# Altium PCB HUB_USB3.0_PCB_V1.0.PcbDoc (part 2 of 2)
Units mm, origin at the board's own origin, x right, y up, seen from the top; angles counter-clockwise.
Board outline 100 x 80 mm, 2 copper layers (Top Layer, Bottom Layer), stack 1.071 mm thick; 154 components, 104 nets, 521 pads, 700 vias.
Unrouted connection lines stored in the file: 114.
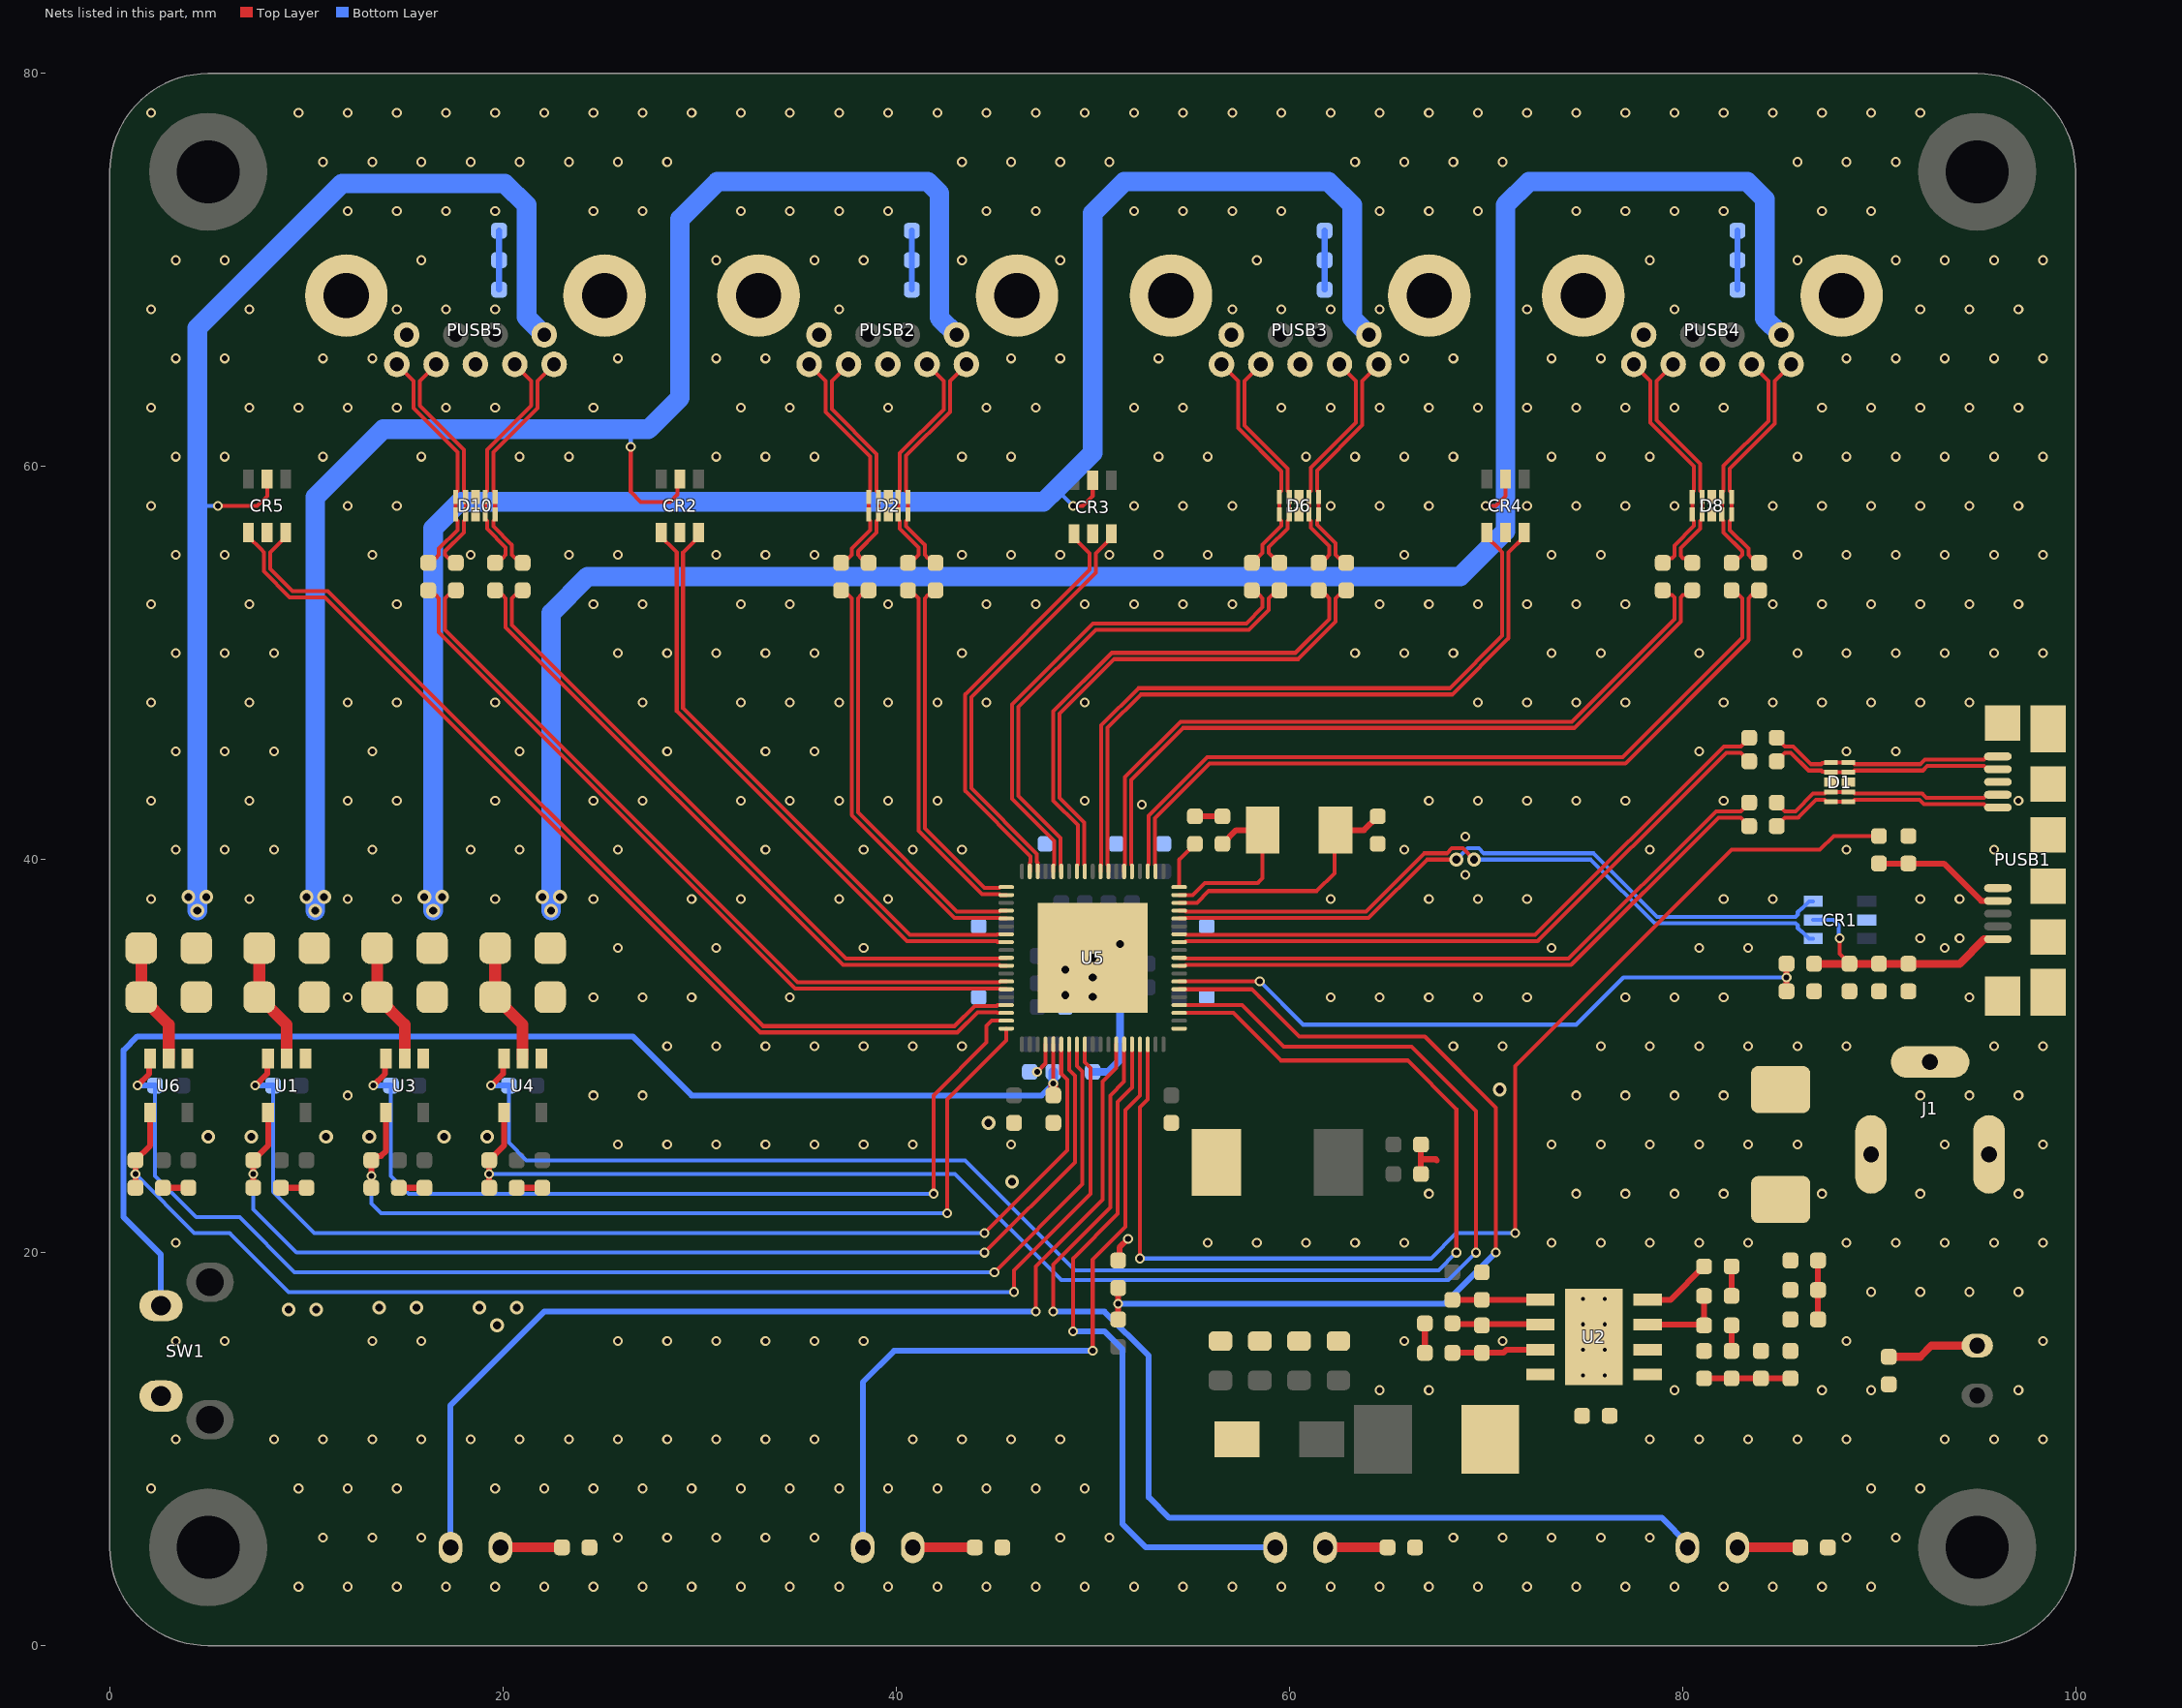
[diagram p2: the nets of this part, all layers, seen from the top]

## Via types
v1: diameter 0.5, hole 0.3, Top Layer to Bottom Layer, tented both sides, 628 vias
v2: diameter 0.7, hole 0.4, Top Layer to Bottom Layer, tented both sides, 40 vias
v3: diameter 0.8, hole 0.5, Top Layer to Bottom Layer, 32 vias

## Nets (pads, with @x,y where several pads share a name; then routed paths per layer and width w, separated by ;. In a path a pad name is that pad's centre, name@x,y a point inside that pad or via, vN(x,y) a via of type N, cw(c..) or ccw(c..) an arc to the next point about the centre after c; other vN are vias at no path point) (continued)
GND: C1.2 C2.2 C3.2 C4.1 C5.2 C6.2 C7.2 C8.2 C9.2 C10.2 C11.1 C12.1 C16.1 C17.1 C18.1 C19.1 C20.1 C21.1 C22.1 C23.1 C24.2 C25.2 C26.1 C27.2 C28.2 C29.2 C30.1 C31.1 C32.1 C33.2 C34.2 C35.2 C36.1 C37.1 C38.1 C41.1 C42.1 C43.1 C45.1 C47.1 C50.1 C51.1 C52.1 C53.1 C54.1 C55.1 C56.1 C59.1 C60.1 C61.1 C62.1 C63.1 C64.1 C65.2 C66.2 C67.2 C68.1 C69.1 C70.1 C71.2 C72.2 C73.2 C74.2 C75.1 C76.2 CR1.2 CR2.2 CR3.2 CR4.2 CR5.2 D1.3 D1.8 D2.3 D2.8 D4.1 D6.3 D6.8 D8.3 D8.8 D10.3 D10.8 J1.2 J1.3 PUSB1.5 PUSB1.8 PUSB1.SH1 PUSB1.SH2 PUSB1.SH3 PUSB1.SH4 PUSB1.SH5 PUSB1.SH6 PUSB1.SH7 PUSB1.SH8 PUSB2.4 PUSB2.7 PUSB2.SH1 PUSB2.SH2 PUSB3.4 PUSB3.7 PUSB3.SH1 PUSB3.SH2 PUSB4.4 PUSB4.7 PUSB4.SH1 PUSB4.SH2 PUSB5.4 PUSB5.7 PUSB5.SH1 PUSB5.SH2 R2.2 R4.1 R7.2 R11.1 R12.2 R13.2 R14.1 R17.1 R18.1 R21.1 R30.1 R31.1 R35.1 R39.2 R40.2 R41.1 SW1.1 U1.2 U2.7 U2.9 U2.V U3.2 U4.2 U5.23 U5.77 U6.2 | length 79.4
  Top Layer w0.2: v1(47.17,29.2) 47.6,29.63 U5.23@47.6,30.601
  Top Layer w0.3: R35.1@2.7,23.3 C64.1@4,23.3 ; R4.1@8.7,23.3 C4.1@10,23.3 ; R17.1@14.7,23.3 C26.1@16,23.3 ; R21.1@20.7,23.3 C32.1@22,23.3 ; R40.2@51.3,19.6 51.36,19.66 51.36,20.26 v1(51.8,20.7) ; R31.1@55.2,42.2 C76.2@56.6,42.2 ; C73.2@66.7,24 66.7,24.75 ; C72.2@66.7,25.5 66.7,24.75 ; 67.5,24.7 67.45,24.75 66.7,24.75 ; C25.2@68.3,14.9 C24.2@69.8,14.9 70.9,14.9 71.065,15.065 U2.7@72.775,15.065 ; C20.1@81.1,13.6 C22.1@85.5,13.6 ; R14.1@82.5,17.8 R12.2@82.5,19.3 ; C1.2@86.9,16.6 C3.2@86.9,19.6
  Top Layer w0.6: C70.1@1.6,35.5 C69.1@1.6,33 3,31.6 U6.2@3,29.875 ; C11.1@7.6,35.5 C12.1@7.6,33 9,31.6 U1.2@9,29.875 ; C31.1@13.6,35.5 C30.1@13.6,33 15,31.6 U3.2@15,29.875 ; C37.1@19.6,35.5 C36.1@19.6,33 21,31.6 U4.2@21,29.875
  Bottom Layer w0.3: C67.2@19.8,69 C66.2@19.8,72 ; C7.2@40.8,69 C5.2@40.8,72 ; C29.2@61.8,69 C27.2@61.8,72 ; C35.2@82.8,69 C34.2@82.8,72
  Bottom Layer w0.4: C41.1@50,29.2 50.8,29.2 51.4,29.8 C53.1@51.4,33.5 ; C43.1@51.4,34.7 51.4,33.7 51.3,33.6 51.3,33.4 51.2,33.3 50.4,33.3 49.6,32.5 C50.1@48.6,32.5 C52.1@48.6,33.7 C38.1@48.6,35.1 48.6,36.2 C61.1@48.4,36.4 C47.1@50.8,36.4 C45.1@52,36.4
  other v1: 9.6,3 12.1,3 14.6,3 17.1,3 19.6,3 22.1,3 24.6,3 27.1,3 29.6,3 32.1,3 34.6,3 37.1,3 39.6,3 42.1,3 44.6,3 47.1,3 49.6,3 52.1,3 54.6,3 57.1,3 59.6,3 62.1,3 64.6,3 67.1,3 69.6,3 72.1,3 74.6,3 77.1,3 79.6,3 82.1,3 84.6,3 87.1,3 89.6,3 10.85,5.5 13.35,5.5 15.85,5.5 25.85,5.5 28.35,5.5 30.85,5.5 33.35,5.5 35.85,5.5 48.35,5.5 50.85,5.5 68.35,5.5 70.85,5.5 73.35,5.5 75.85,5.5 78.35,5.5 88.35,5.5 90.85,5.5 2.1,8 9.6,8 12.1,8 14.6,8 19.6,8 22.1,8 24.6,8 27.1,8 29.6,8 32.1,8 34.6,8 37.1,8 39.6,8 42.1,8 44.6,8 47.1,8 49.6,8 89.6,8 92.1,8 3.35,10.5 8.35,10.5 10.85,10.5 13.35,10.5 15.85,10.5 18.35,10.5 20.85,10.5 23.35,10.5 25.85,10.5 28.35,10.5 30.85,10.5 33.35,10.5 35.85,10.5 40.85,10.5 43.35,10.5 45.85,10.5 48.35,10.5 78.35,10.5 80.85,10.5 83.35,10.5 85.85,10.5 88.35,10.5 93.35,10.5 95.85,10.5 98.35,10.5 64.6,13 67.1,13 79.6,13 87.1,13 89.6,13 97.1,13 3.35,15.5 5.85,15.5 13.35,15.5 15.85,15.5 25.85,15.5 28.35,15.5 30.85,15.5 33.35,15.5 35.85,15.5 38.35,15.5 65.85,15.5 70.85,15.5 88.35,15.5 98.35,15.5 89.6,18 92.1,18 94.6,18 97.1,18 3.35,20.5 55.85,20.5 58.35,20.5 60.85,20.5 63.35,20.5 65.85,20.5 73.35,20.5 75.85,20.5 78.35,20.5 80.85,20.5 83.35,20.5 88.35,20.5 90.85,20.5 93.35,20.5 95.85,20.5 98.35,20.5 67.1,23 74.6,23 77.1,23 79.6,23 82.1,23 87.1,23 92.1,23 97.1,23 25.85,25.5 28.35,25.5 30.85,25.5 33.35,25.5 35.85,25.5 38.35,25.5 40.85,25.5 45.85,25.5 73.35,25.5 75.85,25.5 78.35,25.5 80.85,25.5 83.35,25.5 85.85,25.5 93.35,25.5 98.35,25.5 12.1,28 24.6,28 27.1,28 74.6,28 77.1,28 79.6,28 82.1,28 92.1,28 94.6,28 97.1,28 28.35,30.5 30.85,30.5 33.35,30.5 35.85,30.5 38.35,30.5 40.85,30.5 43.35,30.5 68.35,30.5 70.85,30.5 75.85,30.5 78.35,30.5 80.85,30.5 83.35,30.5 85.85,30.5 88.35,30.5 95.85,30.5 98.35,30.5 12.1,33 24.6,33 27.1,33 29.6,33 34.6,33 62.1,33 64.6,33 67.1,33 69.6,33 72.1,33 77.1,33 79.6,33 82.1,33 94.6,33 25.85,35.5 30.85,35.5 38.35,35.5 73.35,35.5 80.85,35.5 83.35,35.5 93.35,35.5 92.1,36 94.1,36 2.1,38 7.1,38 12.1,38 14.6,38 19.6,38 24.6,38 29.6,38 32.1,38 37.1,38 39.6,38 62.1,38 67.1,38 69.6,38 72.1,38 82.1,38 84.6,38 92.1,38 94.1,38 68.949,39.227 3.35,40.5 5.85,40.5 8.35,40.5 13.35,40.5 18.35,40.5 20.85,40.5 25.85,40.5 33.35,40.5 38.35,40.5 40.85,40.5 43.35,40.5 65.85,40.5 78.35,40.5 88.35,40.5 95.85,40.5 68.959,41.164 52.5,42.8 2.1,43 7.1,43 12.1,43 14.6,43 19.6,43 24.6,43 27.1,43 32.1,43 34.6,43 37.1,43 39.6,43 42.1,43 49.6,43 67.1,43 69.6,43 72.1,43 74.6,43 77.1,43 82.1,43 97.1,43 3.35,45.5 5.85,45.5 8.35,45.5 13.35,45.5 20.85,45.5 28.35,45.5 33.35,45.5 35.85,45.5 80.85,45.5 88.35,45.5 90.85,45.5 2.1,48 7.1,48 12.1,48 14.6,48 19.6,48 27.1,48 32.1,48 34.6,48 37.1,48 39.6,48 42.1,48 44.6,48 49.6,48 69.6,48 72.1,48 74.6,48 77.1,48 82.1,48 84.6,48 87.1,48 89.6,48 92.1,48 94.6,48 3.35,50.5 5.85,50.5 8.35,50.5 25.85,50.5 28.35,50.5 30.85,50.5 33.35,50.5 35.85,50.5 43.35,50.5 63.35,50.5 65.85,50.5 68.35,50.5 73.35,50.5 75.85,50.5 80.85,50.5 85.85,50.5 88.35,50.5 90.85,50.5 93.35,50.5 95.85,50.5 98.35,50.5 2.1,53 7.1,53 14.6,53 24.6,53 27.1,53 32.1,53 34.6,53 39.6,53 44.6,53 47.1,53 49.6,53 52.1,53 54.6,53 57.1,53 64.6,53 67.1,53 69.6,53 72.1,53 74.6,53 77.1,53 84.6,53 87.1,53 89.6,53 92.1,53 94.6,53 97.1,53 3.35,55.5 5.85,55.5 13.35,55.5 18.35,55.5 23.35,55.5 25.85,55.5 30.85,55.5 33.35,55.5 35.85,55.5 43.35,55.5 45.85,55.5 48.35,55.5 50.85,55.5 53.35,55.5 55.85,55.5 65.85,55.5 73.35,55.5 75.85,55.5 85.85,55.5 88.35,55.5 90.85,55.5 93.35,55.5 95.85,55.5 98.35,55.5 2.1,58 12.1,58 14.6,58 52.1,58 54.6,58 57.1,58 62.1,58 64.6,58 67.1,58 72.1,58 74.6,58 77.1,58 79.6,58 84.6,58 87.1,58 89.6,58 92.1,58 94.6,58 97.1,58 3.35,60.5 5.85,60.5 10.85,60.5 15.85,60.5 20.85,60.5 23.35,60.5 30.85,60.5 33.35,60.5 35.85,60.5 43.35,60.5 45.85,60.5 53.35,60.5 55.85,60.5 60.85,60.5 63.35,60.5 65.85,60.5 68.35,60.5 73.35,60.5 75.85,60.5 78.35,60.5 85.85,60.5 88.35,60.5 90.85,60.5 93.35,60.5 95.85,60.5 98.35,60.5 2.1,63 7.1,63 9.6,63 12.1,63 14.6,63 17.1,63 19.6,63 24.6,63 32.1,63 34.6,63 39.6,63 44.6,63 47.1,63 52.1,63 54.6,63 59.6,63 62.1,63 64.6,63 67.1,63 69.6,63 72.1,63 74.6,63 77.1,63 79.6,63 82.1,63 87.1,63 89.6,63 92.1,63 94.6,63 97.1,63 3.35,65.5 5.85,65.5 10.85,65.5 13.35,65.5 25.85,65.5 30.85,65.5 33.35,65.5 45.85,65.5 48.35,65.5 53.35,65.5 65.85,65.5 68.35,65.5 73.35,65.5 75.85,65.5 88.35,65.5 90.85,65.5 93.35,65.5 95.85,65.5 98.35,65.5 2.1,68 7.1,68 14.6,68 17.1,68 19.6,68 37.1,68 57.1,68 59.6,68 62.1,68 64.6,68 72.1,68 79.6,68 92.1,68 94.6,68 97.1,68 3.35,70.5 5.85,70.5 15.85,70.5 30.85,70.5 35.85,70.5 38.35,70.5 43.35,70.5 48.35,70.5 58.35,70.5 78.35,70.5 85.85,70.5 90.85,70.5 93.35,70.5 95.85,70.5 98.35,70.5 12.1,73 14.6,73 17.1,73 19.6,73 24.6,73 27.1,73 32.1,73 34.6,73 37.1,73 39.6,73 44.6,73 47.1,73 52.1,73 54.6,73 57.1,73 59.6,73 64.6,73 67.1,73 69.6,73 74.6,73 77.1,73 79.6,73 82.1,73 87.1,73 89.6,73 10.85,75.5 13.35,75.5 15.85,75.5 18.35,75.5 20.85,75.5 23.35,75.5 25.85,75.5 28.35,75.5 43.35,75.5 45.85,75.5 48.35,75.5 50.85,75.5 63.35,75.5 65.85,75.5 68.35,75.5 70.85,75.5 85.85,75.5 88.35,75.5 90.85,75.5 2.1,78 9.6,78 12.1,78 14.6,78 17.1,78 19.6,78 22.1,78 24.6,78 27.1,78 29.6,78 32.1,78 34.6,78 37.1,78 39.6,78 42.1,78 44.6,78 47.1,78 49.6,78 52.1,78 54.6,78 57.1,78 59.6,78 62.1,78 64.6,78 67.1,78 69.6,78 72.1,78 74.6,78 77.1,78 79.6,78 82.1,78 84.6,78 87.1,78 89.6,78 92.1,78
  other v2: 19.7,16.3 9.1,17.1 10.5,17.1 13.7,17.2 15.6,17.2 18.8,17.2 20.7,17.2 45.9,23.6 5,25.9 7.2,25.9 11,25.9 13.2,25.9 17,25.9 19.2,25.9 44.7,26.6 70.7,28.3 50,33.008 48.6,33.1 50,34 48.6,34.4 50,35 51.4,35.7
HSD1_N: CR2.1 U5.8 | length 31
  Top Layer w0.2: CR2.1@28.05,56.638 28.05,56.43 28.712,55.769 28.84,55.64 28.84,47.56 40.561,35.839 45.123,35.839 45.162,35.8 U5.8@45.601,35.8
HSD1_P: CR2.3 U5.7 | length 30.5
  Top Layer w0.2: CR2.3@29.95,56.638 29.95,56.43 29.16,55.64 29.16,47.693 40.693,36.159 45.123,36.159 45.162,36.199 U5.7@45.601,36.199
HSD2_N: CR3.1 U5.75 | length 21.5
  Top Layer w0.2: U5.75@46.8,39.399 46.8,39.836 46.84,39.876 46.84,40.16 43.5,43.5 43.5,48.4 49.84,54.74 49.84,55.578 49.712,55.706 49.05,56.368 CR3.1@49.05,56.575
HSD2_P: CR3.3 U5.74 | length 21.5
  Top Layer w0.2: U5.74@47.201,39.399 47.201,39.836 47.16,39.876 47.16,40.292 43.82,43.633 43.82,48.267 50.16,54.607 50.16,55.578 50.95,56.368 CR3.3@50.95,56.575
HSD3_N: CR4.1 U5.66 | length 35.3
  Top Layer w0.2: U5.66@50.401,39.399 50.401,39.699 50.441,39.739 50.441,41.722 50.441,46.841 52.32,48.72 68.167,48.72 70.84,51.393 70.84,55.64 70.712,55.769 70.05,56.43 CR4.1@70.05,56.638
HSD3_P: CR4.3 U5.65 | length 35.3
  Top Layer w0.2: U5.65@50.8,39.399 50.8,39.699 50.761,39.739 50.761,41.59 50.761,46.708 52.453,48.4 68.3,48.4 71.16,51.26 71.16,55.64 71.95,56.43 CR4.3@71.95,56.638
HSD4_N: CR5.1 U5.17 | length 50.2
  Top Layer w0.2: CR5.1@7.05,56.638 7.05,56.43 7.712,55.769 7.84,55.64 7.84,54.66 9.15,53.35 10.95,53.35 33.094,31.206 43.106,31.206 44.139,32.239 45.124,32.239 45.164,32.199 U5.17@45.601,32.199
HSD4_P: CR5.3 U5.16 | length 49.7
  Top Layer w0.2: CR5.3@8.95,56.638 8.95,56.43 8.16,55.64 8.16,54.793 9.283,53.67 11.083,53.67 33.226,31.526 42.974,31.526 44.006,32.559 45.124,32.559 45.164,32.6 U5.16@45.601,32.6
LED1: D5.1 U5.35 | length 37.4
  Top Layer w0.2: v1(50,15) 50,19.65 51.66,21.31 51.66,27.26 52.4,28 U5.35@52.4,30.601
  Bottom Layer w0.3: D5.1@38.307,5 38.307,13.407 39.9,15 v1(50,15)
LED2: D7.1 U5.34 | length 35.9
  Top Layer w0.2: v1(49,16) 49,19.7 51.28,21.98 51.28,27.68 51.999,28.399 U5.34@51.999,30.601
  Bottom Layer w0.3: v1(49,16) 50.6,16 51.519,15.081 51.519,6.181 52.7,5 D7.1@59.283,5
LED3: D9.1 U5.33 | length 56.7
  Top Layer w0.2: v1(48,17) 48,19.4 50.9,22.3 50.9,28 51.6,28.7 U5.33@51.6,30.601
  Bottom Layer w0.3: v1(48,17) 50.6,17 52.849,14.751 52.849,7.551 53.9,6.5 78.96,6.5 80.26,5.2 D9.1@80.26,5
LED4: D11.1 U5.32 | length 54.3
  Top Layer w0.2: v1(47.1,17) 47.1,19.3 50.5,22.7 50.5,28.7 51.201,29.401 U5.32@51.201,30.601
  Bottom Layer w0.3: D11.1@17.33,5 17.33,12.23 22.1,17 v1(47.1,17)
LX: L2.1 U5.39
MAIN_D_N: CR1.4 U5.54 | length 35.6
  Top Layer w0.2: U5.54@54.399,37.398 54.699,37.398 54.739,37.358 63.906,37.358 66.867,40.32 68.014,40.32 68.264,40.57 68.83,40.57 v2(69.4,40)
  Bottom Layer w0.2: v2(69.4,40) 75.347,40 78.579,36.768 85.752,36.768 85.869,36.651 85.869,36.525 86.045,36.349 86.077,36.349 86.448,35.978 CR1.4@86.655,35.978
MAIN_D_P: CR1.6 U5.53 | length 35.6
  Top Layer w0.2: U5.53@54.399,36.999 54.699,36.999 54.739,37.038 64.038,37.038 67,40 v2(68.5,40)
  Bottom Layer w0.2: v2(68.5,40) 69.07,40.57 69.636,40.57 69.886,40.32 75.48,40.32 78.712,37.088 85.752,37.088 85.869,37.206 85.869,37.332 86.045,37.507 86.077,37.507 86.448,37.878 CR1.6@86.655,37.878
MAIN_SSRX_N: R5.2 U5.50 | length 33.2
  Top Layer w0.2: U5.50@54.399,35.8 54.699,35.8 54.739,35.839 72.639,35.839 82.24,45.44 82.983,45.44 83.4,45.023 R5.2@83.4,45
MAIN_SSRX_P: R6.2 U5.51 | length 33.2
  Top Layer w0.2: U5.51@54.399,36.199 54.699,36.199 54.739,36.159 72.507,36.159 82.107,45.76 82.983,45.76 83.4,46.177 R6.2@83.4,46.2
MAIN_SSTX_N: C13.2 U5.47 | length 32.3
  Top Layer w0.2: U5.47@54.399,34.599 54.699,34.599 54.74,34.639 74.339,34.639 81.84,42.14 82.983,42.14 83.4,41.723 C13.2@83.4,41.7
MAIN_SSTX_P: C14.2 U5.48 | length 32.3
  Top Layer w0.2: U5.48@54.399,35 54.699,35 54.74,34.959 74.207,34.959 81.707,42.46 82.983,42.46 83.4,42.877 C14.2@83.4,42.9
NetC15_1: C15.1 L1.1 U2.8
NetC15_2: C15.2 U2.1
NetC24_1: C24.1 R9.2 U2.6 | length 4.5
  Top Layer w0.3: R9.2@68.3,16.4 68.332,16.368 72.742,16.368 U2.6@72.775,16.335
NetC25_1: C25.1 R9.1 | length 1.5
  Top Layer w0.3: C25.1@66.9,14.9 R9.1@66.9,16.4
NetD3_2: D3.2 R7.1 | length 4.7
  Top Layer w0.4: R7.1@90.5,14.7 92.1,14.7 92.67,15.27 D3.2@95,15.27
NetD5_2: D5.2 R11.2 | length 3.2
  Top Layer w0.5: D5.2@40.823,5 R11.2@44,5
NetD7_2: D7.2 R18.2 | length 3.2
  Top Layer w0.5: D7.2@61.823,5 R18.2@65,5
NetD9_2: D9.2 R30.2 | length 3.2
  Top Layer w0.5: D9.2@82.823,5 R30.2@86,5
NetD11_2: D11.2 R41.2 | length 3.2
  Top Layer w0.5: D11.2@19.823,5 R41.2@23,5
NetR8_1: R8.1 R13.1 U2.5 | length 4.5
  Top Layer w0.3: R8.1@68.3,17.6 68.302,17.603 72.773,17.603 U2.5@72.775,17.605
NetR10_1: R10.1 R14.2 U2.3 | length 4.4
  Top Layer w0.3: U2.3@78.225,16.335 81.065,16.335 R10.1@81.1,16.3 R14.2@81.1,17.8
NetR12_1: R12.1 U2.4 | length 3.6
  Top Layer w0.3: U2.4@78.225,17.605 79.405,17.605 R12.1@81.1,19.3
NetR31_2: R31.2 U5.57 | length 2.5
  Top Layer w0.2: U5.57@54.399,38.599 54.399,39.999 R31.2@55.2,40.8
NetR34_2: R34.2 U5.36 | length 62.6
  Top Layer w0.2: v1(52.4,19.7) 52.4,27.4 52.799,27.799 U5.36@52.799,30.601 ; v1(71.5,21) 71.5,29.5 82.5,40.5 87,40.5 87.7,41.2 R34.2@90,41.2
  Bottom Layer w0.2: v1(52.4,19.7) 67.2,19.7 68.5,21 v1(71.5,21)
OC_PORT1: R1.2 U1.3 U5.25 | length 56.4
  Top Layer w0.2: v1(44.5,21) 48.7,25.2 48.7,28.8 48.4,29.1 U5.25@48.4,30.601
  Top Layer w0.3: v1(7.4,28.5) 8.001,29.101 U1.3@8.001,29.826
  Bottom Layer w0.2: R1.2@8.3,28.5 8.3,23.1 10.4,21 v1(44.5,21)
  Bottom Layer w0.3: v1(7.4,28.5) R1.2@8.3,28.5
OC_PORT2: R15.2 U3.3 U5.18 | length 45.8
  Top Layer w0.2: v1(41.9,23) 41.9,28 44.6,30.7 44.6,31.537 44.862,31.8 U5.18@45.601,31.8
  Top Layer w0.3: v1(13.4,28.5) 14.001,29.101 U3.3@14.001,29.826
  Bottom Layer w0.2: R15.2@14.3,28.5 14.3,23.9 15.2,23 v1(41.9,23)
  Bottom Layer w0.3: v1(13.4,28.5) R15.2@14.3,28.5
OC_PORT3: R19.2 U4.3 U5.41 | length 80.1
  Top Layer w0.2: U5.41@54.399,32.198 57.152,32.198 59.573,29.778 66.022,29.778 68.5,27.3 v1(68.5,20)
  Top Layer w0.3: v1(19.4,28.5) 20.001,29.101 U4.3@20.001,29.826
  Bottom Layer w0.2: R19.2@20.3,28.5 20.3,25.6 21.2,24.7 43.5,24.7 49.1,19.1 67.6,19.1 v1(68.5,20)
  Bottom Layer w0.3: v1(19.4,28.5) R19.2@20.3,28.5
OC_PORT4: R32.2 U5.27 U6.3 | length 65.4
  Top Layer w0.2: v1(45,19) 49.48,23.48 49.48,29.22 49.2,29.5 U5.27@49.2,30.601
  Top Layer w0.3: v1(1.4,28.5) 2.001,29.101 2.001,29.826 U6.3@2.05,29.875
  Bottom Layer w0.2: R32.2@2.3,28.5 2.3,23.9 4.4,21.8 6.6,21.8 9.4,19 v1(45,19)
  Bottom Layer w0.3: v1(1.4,28.5) R32.2@2.3,28.5
PE_PORT1: R3.2 R4.2 U1.4 U5.26 | length 56.7
  Top Layer w0.2: v1(44.5,20) 49.1,24.6 49.1,29 48.801,29.299 U5.26@48.801,30.601
  Top Layer w0.3: R4.2@7.3,23.3 R3.2@7.3,24.7 8.05,25.45 U1.4@8.05,27.125
  Bottom Layer w0.2: v1(7.3,24) 7.3,22.2 9.5,20 v1(44.5,20)
PE_PORT2: R16.2 R17.2 U3.4 U5.19 | length 46.2
  Top Layer w0.2: v1(42.6,22) 42.6,27.8 45.601,30.801 U5.19@45.601,31.398
  Top Layer w0.3: R17.2@13.3,23.3 R16.2@13.3,24.45 ; U3.4@14.05,27.125 14.05,25.181 13.788,24.919 13.546,24.919 13.45,24.823 R16.2@13.45,24.7 ; R16.2@13.3,24.45 R16.2@13.3,24.7 R16.2@13.45,24.7 ; R16.2@13.3,24.45 13.45,24.6 R16.2@13.45,24.7
  Bottom Layer w0.2: v1(13.3,23.9) 13.3,22.5 13.8,22 v1(42.6,22)
PE_PORT3: R20.2 R21.2 U4.4 U5.42 | length 81.7
  Top Layer w0.2: U5.42@54.399,32.6 57.6,32.6 59.722,30.478 66.222,30.478 69.5,27.2 v1(69.5,20)
  Top Layer w0.3: R21.2@19.3,23.3 v1(19.3,24) R20.2@19.3,24.7 20.05,25.45 U4.4@20.05,27.125
  Bottom Layer w0.2: v1(19.3,24) 43,24 48.4,18.6 68.1,18.6 v1(69.5,20)
PE_PORT4: R33.2 R35.2 U5.28 U6.4 | length 65.7
  Top Layer w0.2: v1(46,18) 46,19.1 49.9,23 49.9,29.4 49.601,29.699 U5.28@49.601,30.601
  Top Layer w0.3: R35.2@1.3,23.3 R33.2@1.3,24.7 2.05,25.45 U6.4@2.05,27.125
  Bottom Layer w0.2: v1(1.3,24) 4.3,21 6.1,21 9.1,18 v1(46,18)
POW_DET: R38.2 R40.1 U5.44 | length 47.9
  Top Layer w0.2: U5.44@54.399,33.4 58.1,33.4 58.5,33 60.5,31 66.9,31 70.517,27.383 v1(70.517,20.017)
  Top Layer w0.3: R38.2@51.3,16.6 v1(51.3,17.4) R40.1@51.3,18.2
  Bottom Layer w0.3: v1(51.3,17.4) 67.9,17.4 v1(70.517,20.017)
RESET: C75.2 R36.2 SW1.2 U5.24 | length 66.1
  Top Layer w0.2: v1(48.001,28.6) U5.24@48.001,30.601
  Top Layer w0.5: C75.2@48,28 v1(48.001,28.6)
  Bottom Layer w0.3: SW1.2@2.6,17.3 2.6,19.9 0.7,21.8 0.7,30.3 1.4,31 26.6,31 29.6,28 47.401,28 v1(48.001,28.6)
  Bottom Layer w0.5: v1(48.001,28.6) R36.2@48,29.2
RX0_N: D1.4 D1.7 PUSB1.9 R5.1 | length 12.1
  Top Layer w0.2: R5.1@84.8,45 84.8,45.023 85.217,45.44 85.507,45.44 86.414,44.533 87.059,44.533 87.122,44.47 87.528,44.47 D1.7@87.555,44.443 88.673,44.443 88.763,44.533 92.233,44.533 92.465,44.765 95.333,44.765 95.498,44.6 PUSB1.9@96.05,44.6
RX0_P: D1.5 D1.6 PUSB1.10 R6.1 | length 12.1
  Top Layer w0.2: R6.1@84.8,46.2 84.8,46.177 85.217,45.76 85.64,45.76 86.547,44.853 87.059,44.853 87.122,44.916 87.529,44.916 D1.6@87.556,44.943 88.673,44.943 88.763,44.853 92.101,44.853 92.332,45.085 95.333,45.085 95.498,45.25 PUSB1.10@96.05,45.25
RX1_N: R23.2 U5.5 | length 21.8
  Top Layer w0.2: R23.2@37.2,53.7 37.438,53.462 37.577,53.462 37.74,53.299 37.74,42.266 42.967,37.038 45.261,37.038 45.301,36.999 U5.5@45.601,36.999
RX1_P: R22.2 U5.4 | length 21.3
  Top Layer w0.2: R22.2@38.6,53.7 38.362,53.462 38.223,53.462 38.06,53.299 38.06,42.398 43.1,37.358 45.261,37.358 45.301,37.398 U5.4@45.601,37.398
RX2_N: R24.1 U5.72 | length 25.4
  Top Layer w0.2: U5.72@48.001,39.399 48.001,39.699 48.04,39.739 48.04,40.96 45.9,43.1 45.9,47.9 50.02,52.02 57.82,52.02 58.64,52.84 58.64,53.299 58.477,53.462 58.338,53.462 R24.1@58.1,53.7
RX2_P: R25.1 U5.71 | length 25.4
  Top Layer w0.2: U5.71@48.4,39.399 48.4,39.699 48.36,39.739 48.36,41.092 46.22,43.233 46.22,47.767 50.153,51.7 57.953,51.7 58.96,52.707 58.96,53.299 59.123,53.462 59.262,53.462 R25.1@59.5,53.7
RX3_N: R28.1 U5.63 | length 37.9
  Top Layer w0.2: U5.63@51.6,39.399 51.6,39.699 51.64,39.739 51.64,44.192 54.467,47.02 74.367,47.02 79.59,52.243 79.59,53.349 79.473,53.466 79.234,53.466 R28.1@79,53.7
RX3_P: R29.1 U5.62 | length 37.9
  Top Layer w0.2: U5.62@51.999,39.399 51.999,39.699 51.96,39.739 51.96,44.06 54.6,46.7 74.5,46.7 79.91,52.11 79.91,53.349 80.027,53.466 80.266,53.466 R29.1@80.5,53.7
RX4_N: R27.2 U5.14 | length 38.8
  Top Layer w0.2: R27.2@16.2,53.7 16.438,53.462 16.577,53.462 16.74,53.299 16.74,51.56 34.861,33.439 45.261,33.439 45.301,33.4 U5.14@45.601,33.4
RX4_P: R26.2 U5.13 | length 38.3
  Top Layer w0.2: R26.2@17.6,53.7 17.362,53.462 17.223,53.462 17.06,53.299 17.06,51.693 34.993,33.759 45.261,33.759 45.301,33.799 U5.13@45.601,33.799
SSRX1_N: D2.5 D2.6 PUSB2.5 R23.1 | length 12.2
  Top Layer w0.2: PUSB2.5@35.577,65.2 36.417,64.36 36.417,62.783 38.69,60.51 38.69,58.763 38.6,58.673 D2.5@38.6,58.445 D2.6@38.6,57.556 38.6,57.327 38.69,57.237 38.69,56.775 37.74,55.825 37.74,55.501 37.577,55.338 37.438,55.338 R23.1@37.2,55.1
SSRX1_P: D2.4 D2.7 PUSB2.6 R22.1 | length 12.2
  Top Layer w0.2: PUSB2.6@37.577,65.2 36.737,64.36 36.737,62.916 39.01,60.643 39.01,58.763 39.1,58.673 D2.4@39.1,58.445 D2.7@39.1,57.556 39.1,57.327 39.01,57.237 39.01,56.643 38.06,55.693 38.06,55.501 38.223,55.338 38.362,55.338 R22.1@38.6,55.1
SSRX2_N: D6.5 D6.6 PUSB3.5 R24.2 | length 12.1
  Top Layer w0.2: PUSB3.5@56.553,65.2 57.393,64.36 57.393,61.954 59.59,59.757 59.59,58.763 59.5,58.673 D6.5@59.5,58.445 D6.6@59.5,57.556 59.5,57.327 59.59,57.237 59.59,56.98 58.64,56.03 58.64,55.6 58.14,55.1 R24.2@58.1,55.1
SSRX2_P: D6.4 D6.7 PUSB3.6 R25.2 | length 12.1
  Top Layer w0.2: PUSB3.6@58.553,65.2 57.713,64.36 57.713,62.087 59.91,59.89 59.91,58.763 60,58.673 D6.4@60,58.445 D6.7@60,57.556 60,57.327 59.91,57.237 59.91,56.847 58.96,55.897 58.96,55.6 59.46,55.1 R25.2@59.5,55.1
SSRX3_N: D8.5 D8.6 PUSB4.5 R28.2 | length 12.2
  Top Layer w0.2: PUSB4.5@77.53,65.2 78.37,64.36 78.37,62.23 80.59,60.01 80.59,58.763 80.5,58.673 D8.5@80.5,58.445 D8.6@80.5,57.556 80.5,57.327 80.59,57.237 80.59,56.98 79.59,55.98 79.59,55.451 79.473,55.334 79.234,55.334 R28.2@79,55.1
SSRX3_P: D8.4 D8.7 PUSB4.6 R29.2 | length 12.2
  Top Layer w0.2: PUSB4.6@79.53,65.2 78.69,64.36 78.69,62.363 80.91,60.143 80.91,58.763 81,58.673 D8.4@81,58.444 D8.7@81,57.556 81,57.327 80.91,57.237 80.91,56.847 79.91,55.847 79.91,55.451 80.027,55.334 80.266,55.334 R29.2@80.5,55.1
SSRX4_N: D10.5 D10.6 PUSB5.5 R27.1 | length 12.2
  Top Layer w0.2: PUSB5.5@14.6,65.2 15.44,64.36 15.44,62.975 17.69,60.725 17.69,58.763 17.6,58.673 D10.5@17.6,58.444 D10.6@17.6,57.556 17.6,57.327 17.69,57.237 17.69,56.775 16.74,55.825 16.74,55.501 16.577,55.338 16.438,55.338 R27.1@16.2,55.1
SSRX4_P: D10.4 D10.7 PUSB5.6 R26.1 | length 12.2
  Top Layer w0.2: PUSB5.6@16.6,65.2 15.76,64.36 15.76,63.107 18.01,60.857 18.01,58.763 18.1,58.673 D10.4@18.1,58.445 D10.7@18.1,57.556 18.1,57.327 18.01,57.237 18.01,56.643 17.06,55.693 17.06,55.501 17.223,55.338 17.362,55.338 R26.1@17.6,55.1
SSTX1_N: C40.1 D2.2 D2.9 PUSB2.8 | length 12.1
  Top Layer w0.2: C40.1@40.6,55.1 40.838,55.338 40.977,55.338 41.14,55.501 41.14,55.88 40.19,56.83 40.19,57.237 40.1,57.327 D2.9@40.1,57.556 D2.2@40.1,58.445 40.1,58.673 40.19,58.763 40.19,60.681 42.417,62.908 42.417,64.36 PUSB2.8@41.577,65.2
SSTX1_P: C39.1 D2.1 D2.10 PUSB2.9 | length 12.1
  Top Layer w0.2: C39.1@42,55.1 41.762,55.338 41.623,55.338 41.46,55.501 41.46,56.013 40.51,56.963 40.51,57.237 40.6,57.327 D2.10@40.6,57.556 D2.1@40.6,58.445 40.6,58.673 40.51,58.763 40.51,60.549 42.737,62.776 42.737,64.36 PUSB2.9@43.577,65.2
SSTX2_N: C44.2 D6.2 D6.9 PUSB3.8 | length 12.2
  Top Layer w0.2: C44.2@61.5,55.1 61.738,55.338 61.877,55.338 62.04,55.501 62.04,55.96 61.103,56.897 61.103,57.224 61,57.327 D6.9@61,57.556 D6.2@61,58.445 61,58.673 61.09,58.763 61.09,59.153 61.09,59.933 63.393,62.236 63.393,64.36 PUSB3.8@62.553,65.2
SSTX2_P: C46.2 D6.1 D6.10 PUSB3.9 | length 12.2
  Top Layer w0.2: C46.2@62.9,55.1 62.662,55.338 62.523,55.338 62.36,55.501 62.36,56.093 61.423,57.03 61.423,57.25 61.5,57.327 D6.10@61.5,57.556 D6.1@61.5,58.445 61.5,58.673 61.41,58.763 61.41,59.02 61.41,59.8 63.713,62.103 63.713,64.36 PUSB3.9@64.553,65.2
SSTX3_N: C57.2 D8.2 D8.9 PUSB4.8 | length 12.2
  Top Layer w0.2: C57.2@82.5,55.1 82.738,55.338 82.877,55.338 83.04,55.501 83.04,55.693 82.09,56.643 82.09,57.237 82,57.327 D8.9@82,57.556 D8.2@82,58.444 82,58.673 82.09,58.763 82.09,59.19 82.09,60.033 84.37,62.313 84.37,64.36 PUSB4.8@83.53,65.2
SSTX3_P: C58.2 D8.1 D8.10 PUSB4.9 | length 12.2
  Top Layer w0.2: C58.2@83.9,55.1 83.662,55.338 83.523,55.338 83.36,55.501 83.36,55.825 82.41,56.775 82.41,57.237 82.5,57.327 D8.10@82.5,57.556 D8.1@82.5,58.445 82.5,58.673 82.41,58.763 82.41,59.057 82.41,59.9 84.69,62.18 84.69,64.36 PUSB4.9@85.53,65.2
SSTX4_N: C49.1 D10.2 D10.9 PUSB5.8 | length 12.2
  Top Layer w0.2: C49.1@19.6,55.1 19.838,55.338 19.977,55.338 20.14,55.501 20.14,55.88 19.19,56.83 19.19,57.237 19.1,57.327 D10.9@19.1,57.556 D10.2@19.1,58.445 19.1,58.673 19.19,58.763 19.19,60.857 21.44,63.107 21.44,64.36 PUSB5.8@20.6,65.2
SSTX4_P: C48.1 D10.1 D10.10 PUSB5.9 | length 12.2
  Top Layer w0.2: C48.1@21,55.1 20.762,55.338 20.623,55.338 20.46,55.501 20.46,56.013 19.51,56.963 19.51,57.237 19.6,57.327 D10.10@19.6,57.556 D10.1@19.6,58.444 19.6,58.673 19.51,58.763 19.51,60.725 21.76,62.975 21.76,64.36 PUSB5.9@22.6,65.2
TX0_N: C13.1 D1.1 D1.10 PUSB1.6 | length 12
  Top Layer w0.2: C13.1@84.8,41.7 84.8,41.723 85.217,42.14 85.893,42.14 86.786,43.033 87.237,43.033 87.327,42.943 D1.1@88.444,42.943 88.673,42.943 88.763,43.033 92.067,43.033 92.285,42.815 95.333,42.815 95.498,42.65 PUSB1.6@96.05,42.65
TX0_P: C14.1 D1.2 D1.9 PUSB1.7 | length 12
  Top Layer w0.2: C14.1@84.8,42.9 84.8,42.877 85.217,42.46 85.76,42.46 86.653,43.353 87.237,43.353 87.327,43.443 D1.9@87.555,43.443 D1.2@88.444,43.443 88.673,43.443 88.763,43.353 92.199,43.353 92.418,43.135 95.333,43.135 95.498,43.3 PUSB1.7@96.05,43.3
TX1_N: C40.2 U5.2 | length 18.4
  Top Layer w0.2: C40.2@40.6,53.7 40.838,53.462 40.977,53.462 41.14,53.299 41.14,41.466 44.367,38.239 44.848,38.239 45.26,38.239 45.301,38.198 U5.2@45.601,38.198
TX1_P: C39.2 U5.1 | length 17.8
  Top Layer w0.2: C39.2@42,53.7 41.762,53.462 41.623,53.462 41.46,53.299 41.46,41.599 44.5,38.559 44.981,38.559 45.26,38.559 45.301,38.599 U5.1@45.601,38.599
TX2_N: C44.1 U5.69 | length 26.4
  Top Layer w0.2: U5.69@49.2,39.399 49.2,39.699 49.241,39.74 49.241,41.759 48,43 48,47.553 50.967,50.52 52.467,50.52 52.967,50.52 60.32,50.52 62.04,52.24 62.04,53.299 61.877,53.462 61.738,53.462 C44.1@61.5,53.7
TX2_P: C46.1 U5.68 | length 26.4
  Top Layer w0.2: U5.68@49.601,39.399 49.601,39.699 49.561,39.74 49.561,41.892 48.32,43.133 48.32,47.42 51.1,50.2 60.453,50.2 62.36,52.107 62.36,53.299 62.523,53.462 62.662,53.462 C46.1@62.9,53.7
TX3_N: C57.1 U5.60 | length 39.5
  Top Layer w0.2: U5.60@52.799,39.399 52.799,39.699 52.84,39.74 52.84,42.24 55.82,45.22 76.967,45.22 83.04,51.293 83.04,53.299 82.877,53.462 82.738,53.462 C57.1@82.5,53.7
TX3_P: C58.1 U5.59 | length 39.5
  Top Layer w0.2: U5.59@53.2,39.399 53.2,39.699 53.16,39.74 53.16,42.107 55.953,44.9 77.1,44.9 83.36,51.16 83.36,53.299 83.523,53.462 83.662,53.462 C58.1@83.9,53.7
TX4_N: C49.2 U5.11 | length 34.8
  Top Layer w0.2: C49.2@19.6,53.7 19.838,53.462 19.977,53.462 20.14,53.299 20.14,51.807 37.308,34.639 45.26,34.639 45.301,34.599 U5.11@45.601,34.599
TX4_P: C48.2 U5.10 | length 34.3
  Top Layer w0.2: C48.2@21,53.7 20.762,53.462 20.623,53.462 20.46,53.299 20.46,51.94 37.441,34.959 45.26,34.959 45.301,35 U5.10@45.601,35
USB_ID: PUSB1.4 R2.1 R34.1 | length 6.8
  Top Layer w0.3: R34.1@90,39.8 R2.1@91.5,39.8 93.3,39.8 95.2,37.9 PUSB1.4@96.05,37.9
VBUS: C8.1 C9.1 C10.1 CR1.5 PUSB1.1 R37.1 | length 13.5
  Top Layer w0.2: v1(88,36) 88,35.2 C10.1@88.5,34.7
  Top Layer w0.4: R37.1@86.7,34.7 C10.1@88.5,34.7 C8.1@90,34.7 C9.1@91.5,34.7 94.1,34.7 95.35,35.95 PUSB1.1@96.05,35.95
  Bottom Layer w0.2: CR1.5@86.655,36.928 87.672,36.928 87.943,36.657 87.943,36.057 v1(88,36)
VBUS_DET: R37.2 R39.1 U5.45 | length 34.2
  Top Layer w0.2: U5.45@54.399,33.799 v1(58.5,33.8) v1(58.5,33.8)
  Top Layer w0.3: R39.1@85.3,33.3 v1(85.3,34) R37.2@85.3,34.7
  Bottom Layer w0.2: v1(58.5,33.8) 60.7,31.6 74.6,31.6 77,34 v1(85.3,34)
VBUS_Port1: C5.1 C6.1 C7.1 C11.2 C12.2 CR2.5 PUSB2.1 U1.1 | length 79.4
  Top Layer w0.2: v1(26.5,61) 26.5,58.7 27,58.2 28.5,58.2 28.876,58.576 28.876,59.239 CR2.5@29,59.362
  Bottom Layer w0.2: v1(26.5,61) 26.5,61.8 26.6,61.9
  Bottom Layer w1: v2(10.45,37.4) 10.45,58.45 13.9,61.9 26.6,61.9 27.4,61.9 29,63.5 29,72.6 30.9,74.5 41.614,74.5 42.2,73.914 C5.1@42.2,72 C6.1@42.2,70.5 C7.1@42.2,69 42.2,67.577 PUSB2.1@43.077,66.7
  other v2: 10,38.1 10.9,38.1
VBUS_Port2: C27.1 C28.1 C29.1 C30.2 C31.2 CR3.5 PUSB3.1 U3.1 | length 91.3
  Top Layer w0.2: v1(49,58) 49.5,58 50,58.5 CR3.5@50,59.3
  Bottom Layer w0.2: 48.15,58.85 v1(49,58)
  Bottom Layer w1: v2(16.45,37.4) 16.45,56.85 17.8,58.2 47.5,58.2 48.15,58.85 50,60.7 50,72.9 51.6,74.5 62,74.5 63.2,73.3 C27.1@63.2,72 C29.1@63.2,69 63.2,67.553 PUSB3.1@64.053,66.7
  other v2: 16,38.1 16.9,38.1
VBUS_Port3: C33.1 C34.1 C35.1 C36.2 C37.2 CR4.5 PUSB4.1 U4.1 | length 106.3
  Top Layer w0.2: v1(70,58) 70.5,58 71,58.5 CR4.5@71,59.362
  Bottom Layer w0.2: v1(70,58) 71,58
  Bottom Layer w1: v2(22.45,37.4) 22.45,52.55 24.3,54.4 68.7,54.4 71,56.7 71,58 71,73.3 72.2,74.5 83.3,74.5 84.2,73.6 C34.1@84.2,72 C35.1@84.2,69 84.2,67.53 PUSB4.1@84.973,66.757
  other v2: 22,38.1 22.9,38.1
VBUS_Port4: C65.1 C66.1 C67.1 C69.2 C70.2 CR5.5 PUSB5.1 U6.1 | length 61.5
  Top Layer w0.2: v1(5.5,58) 7.5,58 8,58.5 CR5.5@8,59.362
  Bottom Layer w0.2: 4.45,58 v1(5.5,58)
  Bottom Layer w1: v2(4.45,37.4) 4.45,38.1 4.45,58 4.45,67.05 11.8,74.4 20.1,74.4 21.2,73.3 C66.1@21.2,72 C65.1@21.2,70.5 C67.1@21.2,69 21.2,67.6 PUSB5.1@22.1,66.7
  other v2: 4,38.1 4.9,38.1
VCC: C1.1 C2.1 C3.1 C20.2 C21.2 C22.2 C23.2 F1.2 R10.2 U2.2 | length 1.3
  Top Layer w0.3: C23.2@82.5,15 R10.2@82.5,16.3
VIN: F1.1 J1.1
XI: C74.1 U5.55 X1.2 | length 13.2
  Top Layer w0.2: U5.55@54.399,37.799 55.299,37.799 55.9,38.4 61.4,38.4 62.3,39.3 62.3,41.446 X1.2@62.354,41.5
  Top Layer w0.3: X1.2@62.354,41.5 63.8,41.5 C74.1@64.5,42.2
XO: C76.1 U5.56 X1.1 | length 9.4
  Top Layer w0.2: U5.56@54.399,38.198 55.098,38.198 55.7,38.8 58.4,38.8 58.646,39.046 X1.1@58.646,41.5
  Top Layer w0.3: C76.1@56.6,40.8 57.3,41.5 X1.1@58.646,41.5
pads on no net: M1.1 M2.1 M3.1 M4.1 SW1. U5.30 U5.31 U5.37
copper on no net:
  other v3: 5,2.6 95,2.6 3.303,3.303 6.697,3.303 93.303,3.303 96.697,3.303 2.6,5 7.4,5 92.6,5 97.4,5 3.303,6.697 6.697,6.697 93.303,6.697 96.697,6.697 5,7.4 95,7.4 5,72.6 95,72.6 3.303,73.303 6.697,73.303 93.303,73.303 96.697,73.303 2.6,75 7.4,75 92.6,75 97.4,75 3.303,76.697 6.697,76.697 93.303,76.697 96.697,76.697 5,77.4 95,77.4

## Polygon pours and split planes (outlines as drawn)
GND on Top Layer "GND_L01_P002" (solid, remove dead copper, pour order 2): 0,5 0,75 cw(c5,75) 5,80 95,80 cw(c95,75) 100,75 100,5 cw(c95,5) 95,0 5,0 cw(c5,5)
1.1V on Top Layer "1.1V_L01_P001" (solid, remove dead copper, pour order 1): 61.2,22.9 61.2,26.3 65.5,26.3 65.5,22.9
LX on Top Layer "LX_L01_P000" (solid, remove dead copper, pour order 0): 55,30.3 55,22.9 57.6,22.9 57.6,29.9 56,31.5 54,31.5 54,31.3
GND on Bottom Layer "GND_L02_P003" (solid, remove dead copper, pour order 3): 0,5 0,75 cw(c5,75) 5,80 95,80 cw(c95,75) 100,75 100,5 cw(c95,5) 95,0 5,0 cw(c5,5)

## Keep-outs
Keep-Out Layer:
  the board outline again, w0.2

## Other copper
Top Layer:
  rectangle net 1.1V: 64.5,22 65.7,26.3
  rectangle net VBUS_Port3: 21.6,29.3 23.3,38.5
  rectangle net VBUS_Port2: 15.6,29.3 17.3,38.5
  rectangle net VBUS_Port1: 9.6,29.3 11.3,38.5
  rectangle net VBUS_Port4: 3.6,29.3 5.3,38.5
  rectangle net NetC15_2: 75.8,11.2 79,12.2
  rectangle net NetC15_2: 77.4,11.2 79,14.2
  rectangle net VCC: 84.5,14.7 86,23.9
  rectangle net VCC: 77.4,14.6 86,15.5
  pour cut-out: 68.1,26.4 64.5,26.4 64.5,27.306 68.1,27.306
  pour cut-out: 61.2,22.594 57.6,22.594 57.6,23.5 61.2,23.5
  pour cut-out: 20,33.9 20,34.5 20.3,34.5 20.3,33.9
  pour cut-out: 14,33.9 14,34.5 14.3,34.5 14.3,33.9
  pour cut-out: 8,33.9 8,34.5 8.3,34.5 8.3,33.9
  pour cut-out: 20.7,29.4 21.3,29.4 21.3,29.1 20.7,29.1
  pour cut-out: 14.7,29.4 15.3,29.4 15.3,29.1 14.7,29.1
  pour cut-out: 8.7,29.4 9.3,29.4 9.3,29.1 8.7,29.1
  pour cut-out: 2.7,29.4 3.3,29.4 3.3,29.1 2.7,29.1
  region net 5V: 53.5,31 53.5,27.8 53.7,27.6 54.3,27.6 54.5,27.8 54.5,29.6 53.8,30.3 53.8,31
  region net 5V: 46.5,31 46.5,27.8 46.3,27.6 45.7,27.6 45.5,27.8 45.5,29.6 46.2,30.3 46.2,31
  region net 5V: 5.1,23 5.1,21.9 7.4,19.6 7.4,12.9 8.5,12.9 8.5,20.2 6.2,22.5 6.2,23
  region net 5V: 3.5,27.7 3.5,24.2 4.9,24.2 5.1,24 5.1,22 6.2,22 6.2,24.9 5.9,25.2 4.3,25.2 4.3,27.7
  region net 5V: 9.5,27.7 9.5,24.2 10.9,24.2 11.1,24 11.1,12.9 12.2,12.9 12.2,24.9 11.9,25.2 10.3,25.2 10.3,27.7
  region net 5V: 15.5,27.7 15.5,24.2 16.9,24.2 17.1,24 17.1,12.9 18.2,12.9 18.2,24.9 17.9,25.2 16.3,25.2 16.3,27.7
  region net 5V: 21.5,27.7 21.5,24.2 22.9,24.2 23.1,24 23.1,12.9 24.2,12.9 24.2,24.9 23.9,25.2 22.3,25.2 22.3,27.7
  region net 5V: 66.3,8.7 60.6,8.7 60.4,8.9 60.4,12.6 60.1,12.9 7.4,12.9 7.4,14.5 63.2,14.5 63.2,12.3 66.3,12.3
  region net NetC15_1: 73.6,14.2 73.6,12.8 74.2,12.2 75.4,12.2 75.4,9 75.1,8.7 68.7,8.7 68.7,12.5 71.6,12.5 72,12.9 72,14.2
  region net VIN: 83.5,29.5 89,29.5 90.5,28 90.5,23 88,23 88,26.2 87.2,27 83.5,27
Bottom Layer:
  rectangle net 1.1V: 64.5,22 65.7,23.7
  rectangle net VBUS_Port3: 21.6,37 23.3,38.5
  rectangle net VBUS_Port2: 15.6,37 17.3,38.5
  rectangle net VBUS_Port1: 9.6,37 11.3,38.5
  rectangle net VBUS_Port4: 3.6,37 5.3,38.5

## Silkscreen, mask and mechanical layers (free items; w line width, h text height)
Top Overlay:
  drawing of 43 lines, arcs and shapes, not listed
  text "HUB_USB3.0_V1.0" at 97.367,56.8 h1 r90
  text "Design By : AliNik" at 99.267,56.8 h1 r90
  text "RESET" at 5.2,16.9 h1 r270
